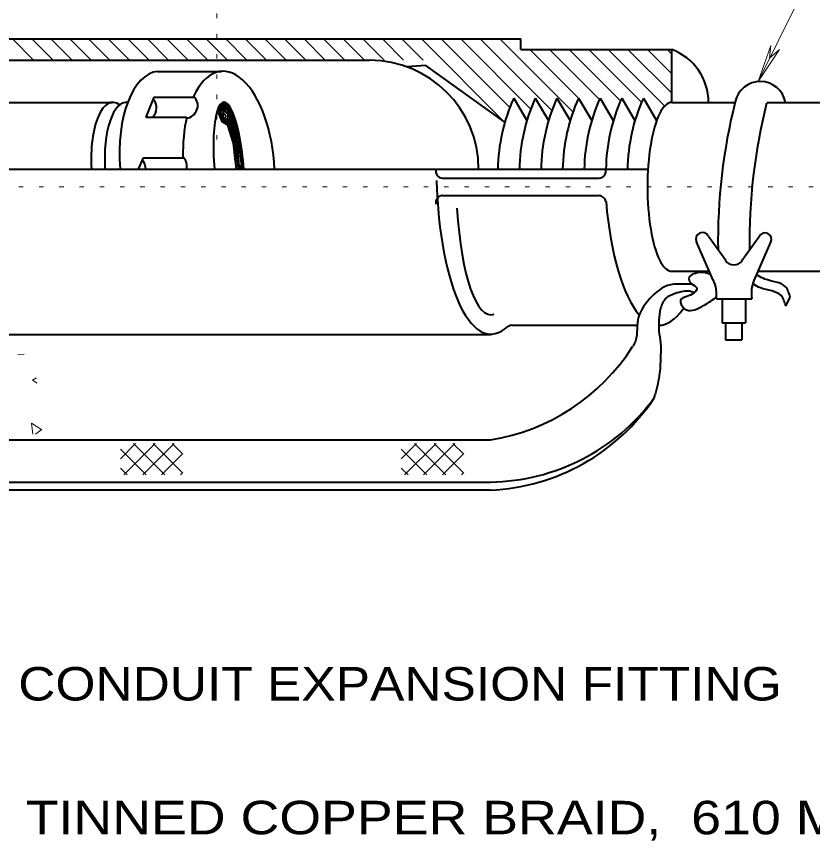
# Model space of a CAD drawing. Extents: x 312583 to 312854, y 144419 to 144597.
# Drawn here: x 312729.23 to 312747.3, y 144539.88 to 144558.59 of the extents above; entities that cross this region are included whole.
import ezdxf

# ---------------------------------------------------------------- set-up
doc = ezdxf.new("R2010")
doc.units = 0
doc.header["$LTSCALE"] = 0.3
doc.linetypes.add('DOTTED', pattern=[1.5, 0.3, -1.2])
doc.layers.add('1', color=7, linetype='Continuous', lineweight=40)
doc.layers.add('2', color=7, linetype='Continuous', lineweight=13)

msp = doc.modelspace()

# ---------------------------------------------------------------- linework, layer by layer
at = {"layer": '1'}
for p, q in [((312727.4098, 144558.076), (312740.6808, 144558.076)), ((312740.6808, 144557.8383), (312740.6808, 144558.076)), ((312740.6808, 144557.8383), (312744.1078, 144557.8383)), ((312744.1078, 144556.6347), (312744.1078, 144557.8383)), ((312724.8721, 144557.593), (312737.2461, 144557.593)), ((312732.4391, 144557.34), (312733.8804, 144557.34)), ((312715.7104, 144556.6347), (312731.4041, 144556.6347)), ((312732.3471, 144556.7573), (312732.1631, 144556.2973)), ((312732.3471, 144556.7573), (312733.2671, 144556.7573)), ((312740.5198, 144556.7343), (312740.8188, 144556.2207)), ((312741.0104, 144556.7343), (312741.3094, 144556.2207)), ((312741.5011, 144556.7343), (312741.8001, 144556.2207)), ((312741.9918, 144556.7343), (312742.2908, 144556.2207)), ((312742.4824, 144556.7343), (312742.7814, 144556.2207)), ((312742.9731, 144556.7343), (312743.2721, 144556.2207)), ((312743.4638, 144556.7343), (312743.7628, 144556.2207)), ((312744.1078, 144556.6347), (312745.5414, 144556.6347)), ((312746.2698, 144556.6347), (312753.1391, 144556.6347)), ((312732.1631, 144556.2973), (312733.0908, 144556.2973)), ((312732.1018, 144555.3773), (312731.9944, 144555.1167)), ((312732.1018, 144555.3773), (312733.0218, 144555.3773)), ((312726.1371, 144555.1167), (312743.5711, 144555.1167)), ((312738.9021, 144554.9173), (312742.4594, 144554.9173)), ((312738.9021, 144554.5187), (312742.4594, 144554.5187)), ((312745.0508, 144552.602), (312744.6674, 144553.4683)), ((312745.3344, 144553.0467), (312744.9434, 144553.591)), ((312745.7024, 144553.0467), (312746.0934, 144553.591)), ((312745.9784, 144552.5943), (312746.3618, 144553.4607)), ((312744.1078, 144552.8013), (312744.9588, 144552.8013)), ((312746.0704, 144552.8013), (312753.1391, 144552.8013)), ((312745.1274, 144552.1727), (312745.9248, 144552.1727)), ((312745.2501, 144552.165), (312745.2501, 144551.6283)), ((312745.7791, 144552.165), (312745.7791, 144551.6283)), ((312746.6991, 144552.0117), (312746.7988, 144552.211)), ((312740.4738, 144551.5747), (312743.3258, 144551.5747)), ((312745.2501, 144551.6283), (312745.7791, 144551.6283)), ((312745.3268, 144551.6283), (312745.3268, 144551.245)), ((312745.7024, 144551.6283), (312745.7024, 144551.245)), ((312726.9498, 144551.3677), (312739.9908, 144551.3677)), ((312745.3268, 144551.245), (312745.7024, 144551.245)), ((312723.0398, 144548.9757), (312739.9908, 144548.9757)), ((312723.0398, 144548.0173), (312739.9908, 144548.0173)), ((312723.0398, 144547.841), (312739.9908, 144547.841))]:
    msp.add_line(p, q, dxfattribs=at)
at = {"layer": '1', "linetype": 'DOTTED', "lineweight": 13}
msp.add_line((312711.3404, 144554.718), (312753.1391, 144554.718), dxfattribs=at)
at = {"layer": '1'}
for points in [[(312740.3204, 144556.19), (312738.5264, 144557.4703), (312738.0971, 144557.4397)], [(312734.3864, 144555.1167), (312734.2254, 144555.1167), (312734.1948, 144555.362), (312734.1564, 144555.707), (312734.0261, 144556.121), (312733.9034, 144556.19), (312733.8498, 144556.328), (312733.7884, 144556.4123), (312733.8804, 144556.5887), (312733.9571, 144556.6117), (312734.0951, 144556.466), (312734.1794, 144556.2053), (312734.2944, 144555.7683), (312734.3328, 144555.431), (312734.3634, 144555.1473), (312734.2714, 144555.1397), (312734.2024, 144555.6533), (312734.0491, 144556.121), (312733.9264, 144556.1977), (312733.8804, 144556.3587), (312733.8191, 144556.3817), (312733.9034, 144556.5503), (312733.9571, 144556.581), (312734.0721, 144556.466), (312734.2714, 144555.73), (312734.3404, 144555.1857), (312734.2868, 144555.1857), (312734.2484, 144555.6763), (312734.0874, 144556.121), (312733.9188, 144556.213), (312733.9188, 144556.3663), (312733.8574, 144556.4123), (312733.9494, 144556.5503), (312734.0184, 144556.4507), (312734.2254, 144555.776), (312734.0414, 144556.1977), (312733.9648, 144556.213), (312733.9801, 144556.3357), (312733.9188, 144556.397), (312733.9571, 144556.4507), (312734.0031, 144556.3893), (312734.0721, 144556.4353), (312734.0798, 144556.2513), (312734.0261, 144556.2207), (312734.0338, 144556.3357), (312734.0414, 144556.466), (312733.9188, 144556.489), (312733.9111, 144556.282), (312734.0031, 144556.2513), (312734.0951, 144556.1593)]]:
    msp.add_lwpolyline(points, dxfattribs=at)
for centre, radius, start, end in [((312743.6525, 144556.6292), 1.292, 0.24072, 69.36647), ((312737.2461, 144555.1167), 2.4763, 0, 90), ((312746.1187, 144556.5275), 0.5827, 10.59906, 167.86288), ((312732.1141, 144556.512), 0.2945, 313.20051, 42.47617), ((312733.0494, 144556.5657), 0.2945, 277.96991, 42.47617), ((312744.2408, 144555.055), 4.0824, 155.71072, 179.13516), ((312744.7315, 144555.055), 4.0824, 155.71072, 179.13516), ((312745.2222, 144555.055), 4.0824, 155.71072, 179.13516), ((312745.7128, 144555.055), 4.0824, 155.71072, 179.13516), ((312746.2035, 144555.055), 4.0824, 155.71072, 179.13516), ((312746.6942, 144555.055), 4.0824, 155.71072, 179.13516), ((312747.1848, 144555.055), 4.0824, 155.71072, 179.13516), ((312758.1933, 144553.4784), 13.0359, 165.91883, 180.82259), ((312758.9063, 144553.4477), 13.0359, 165.91883, 180.72864), ((312731.8687, 144555.132), 0.2945, 357.01533, 42.47617), ((312732.8041, 144555.1857), 0.2945, 346.44908, 42.47617), ((312738.9021, 144555.0707), 0.1533, 165.25644, 270), ((312742.4594, 144555.0707), 0.1533, 270, 14.74356), ((312738.9021, 144554.3653), 0.1533, 90, 194.74356), ((312742.4594, 144554.3653), 0.1533, 6.34019, 90), ((312744.8054, 144553.5297), 0.151, 27.89727, 203.96249), ((312746.2238, 144553.522), 0.151, 336.03751, 152.10273), ((312745.5184, 144553.1771), 0.23, 215.31121, 324.68879), ((312744.2841, 144552.257), 0.8438, 354.28941, 24.22774), ((312746.7604, 144552.2953), 0.8438, 159.26129, 188.35075), ((312740.4738, 144551.4213), 0.1533, 90, 126.8699), ((312739.2535, 144553.6179), 4.7005, 279.02485, 327.49763), ((312739.928, 144552.7174), 4.7005, 270.76554, 323.52738), ((312739.7975, 144552.5321), 4.7005, 272.35877, 326.33013), ((312743.2223, 144550.1142), 0.5218, 338.90205, 347.69946)]:
    msp.add_arc(centre, radius, start, end, dxfattribs=at)
for centre, major_axis, ratio, start_param, end_param in [((312732.609, 144555.1982), (-0.1699, 2.1418), 0.480227, 6.2831853, 7.8539816), ((312734.0503, 144555.1982), (-0.1699, 2.1418), 0.480227, 4.6363619, 6.991541), ((312731.4773, 144555.1827), (-0.0732, 1.452), 0.377783, 5.9815228, 7.8802166), ((312731.784, 144555.1827), (-0.0732, 1.452), 0.377783, 6.2064649, 7.8802166), ((312734.0503, 144555.1982), (-0.1145, 1.4434), 0.228731, 4.6374354, 7.8923792), ((312744.1078, 144554.718), (0, 1.9167), 0.288, 6.2831853, 9.424778), ((312734.0503, 144555.1982), (-0.1699, 2.1418), 0.480227, 0.9927836, 1.4420674), ((312740.0903, 144555.5141), (-0.0995, -4.1388), 0.320432, 4.8776978, 6.5794282), ((312743.9006, 144555.7134), (-0.0995, -4.1388), 0.320432, 5.047256, 5.9492776), ((312740.0903, 144555.5141), (-0.089, -3.7001), 0.239872, 5.0717848, 6.3660556), ((312743.9006, 144555.7134), (-0.0995, -4.1388), 0.320432, 0.0115571, 0.4347576)]:
    msp.add_ellipse(centre, major_axis=major_axis, ratio=ratio, start_param=start_param, end_param=end_param, dxfattribs=at)
for points in [[(312745.0048, 144552.7247), (312744.7211, 144552.7707), (312744.4988, 144552.6327), (312744.5601, 144552.5177), (312744.6751, 144552.4257), (312744.5754, 144552.28), (312744.3071, 144552.142), (312744.3991, 144551.9503), (312744.7824, 144551.9963), (312745.1121, 144552.2033)], [(312746.7988, 144552.211), (312746.6914, 144552.4487), (312746.2238, 144552.625), (312746.0628, 144552.7093)], [(312744.5678, 144552.51), (312744.2534, 144552.51), (312744.0771, 144552.4947), (312743.6018, 144552.1727), (312743.3411, 144551.6973), (312743.2568, 144551.153), (312743.2184, 144551.0917)], [(312746.6991, 144552.0117), (312746.5918, 144552.2493), (312746.1241, 144552.4257), (312745.9631, 144552.51)], [(312744.6061, 144552.3183), (312744.5141, 144552.349), (312744.3684, 144552.3413), (312744.1844, 144552.2953), (312743.9851, 144552.1957), (312743.8548, 144551.9657), (312743.8164, 144551.6897), (312743.8164, 144551.452), (312743.8548, 144551.1683), (312743.8548, 144550.9), (312743.8318, 144550.486), (312743.7321, 144550.003)]]:
    msp.add_spline(points, degree=3, dxfattribs=at)
at = {"layer": '2', "linetype": 'DOTTED'}
msp.add_line((312733.7808, 144555.7913), (312733.7808, 144564.9453), dxfattribs=at)
at = {"layer": '2'}
for p, q in [((312748.2938, 144561.5873), (312746.0704, 144557.11)), ((312729.6178, 144557.593), (312729.1348, 144558.076)), ((312730.0624, 144557.593), (312729.5794, 144558.076)), ((312730.4918, 144557.593), (312730.0088, 144558.076)), ((312730.9211, 144557.593), (312730.4381, 144558.076)), ((312731.3504, 144557.593), (312730.8674, 144558.076)), ((312731.7951, 144557.593), (312731.3121, 144558.076)), ((312732.2398, 144557.593), (312731.7568, 144558.076)), ((312732.6844, 144557.593), (312732.2014, 144558.076)), ((312733.1291, 144557.593), (312732.6461, 144558.076)), ((312733.5738, 144557.593), (312733.0908, 144558.076)), ((312734.0184, 144557.593), (312733.5354, 144558.076)), ((312734.4631, 144557.593), (312733.9801, 144558.076)), ((312734.9078, 144557.593), (312734.4248, 144558.076)), ((312735.3524, 144557.593), (312734.8694, 144558.076)), ((312735.7971, 144557.593), (312735.3141, 144558.076)), ((312736.2418, 144557.593), (312735.7588, 144558.076)), ((312736.6864, 144557.593), (312736.2034, 144558.076)), ((312737.1311, 144557.593), (312736.6481, 144558.076)), ((312737.5758, 144557.593), (312737.0928, 144558.076)), ((312738.0204, 144557.593), (312737.5374, 144558.076)), ((312738.4651, 144557.593), (312737.9821, 144558.076)), ((312740.2974, 144556.2053), (312738.4268, 144558.076)), ((312740.4278, 144556.5197), (312738.8714, 144558.076)), ((312740.9108, 144556.4813), (312739.3161, 144558.076)), ((312741.3861, 144556.4507), (312739.7608, 144558.076)), ((312741.8614, 144556.42), (312740.2054, 144558.076)), ((312746.0704, 144557.11), (312746.3618, 144557.9303)), ((312746.3618, 144557.9303), (312746.3311, 144557.639)), ((312741.9918, 144556.7343), (312740.8878, 144557.8383)), ((312742.4671, 144556.7037), (312741.3324, 144557.8383)), ((312742.9424, 144556.673), (312741.7771, 144557.8383)), ((312743.4254, 144556.6347), (312742.2218, 144557.8383)), ((312743.9468, 144556.558), (312742.6664, 144557.8383)), ((312744.1078, 144556.8417), (312743.1111, 144557.8383)), ((312744.1078, 144557.2863), (312743.5558, 144557.8383)), ((312744.1078, 144557.731), (312744.0004, 144557.8383)), ((312746.0704, 144557.11), (312746.5534, 144557.8383)), ((312746.5534, 144557.8383), (312746.3311, 144557.639)), ((312729.2574, 144550.9153), (312729.4031, 144550.923)), ((312731.5881, 144548.5463), (312731.9331, 144548.8913)), ((312732.1708, 144548.1783), (312731.5881, 144548.761)), ((312731.6648, 144548.1783), (312732.3778, 144548.8913)), ((312732.6001, 144548.1783), (312731.8871, 144548.8913)), ((312732.0941, 144548.1783), (312732.8071, 144548.8913)), ((312733.0064, 144548.2167), (312732.3318, 144548.8913)), ((312733.0064, 144548.646), (312732.7611, 144548.8913)), ((312737.9668, 144548.5463), (312738.3118, 144548.8913)), ((312738.5494, 144548.1783), (312737.9668, 144548.761)), ((312738.0434, 144548.1783), (312738.7564, 144548.8913)), ((312738.9788, 144548.1783), (312738.2658, 144548.8913)), ((312738.4728, 144548.1783), (312739.1858, 144548.8913)), ((312739.3851, 144548.2167), (312738.7104, 144548.8913)), ((312739.3851, 144548.646), (312739.1398, 144548.8913)), ((312732.5234, 144548.1783), (312733.0064, 144548.6613)), ((312738.9021, 144548.1783), (312739.3851, 144548.6613)), ((312731.7414, 144548.1783), (312731.5881, 144548.3317)), ((312732.9528, 144548.1783), (312733.0064, 144548.232)), ((312738.1201, 144548.1783), (312737.9668, 144548.3317)), ((312739.3314, 144548.1783), (312739.3851, 144548.232))]:
    msp.add_line(p, q, dxfattribs=at)
for points in [[(312729.6868, 144550.3863), (312729.5948, 144550.3327), (312729.7021, 144550.2637)], [(312729.8018, 144549.2057), (312729.7788, 144549.221), (312729.5718, 144549.3513), (312729.6024, 144549.106)], [(312729.6638, 144549.106), (312729.7788, 144549.198), (312729.8018, 144549.2057)]]:
    msp.add_lwpolyline(points, dxfattribs=at)

# ---------------------------------------------------------------- texts
for s, width, p in [('CONDUIT EXPANSION FITTING', 1.15, (312729.2693, 144543.0576)), ('TINNED COPPER BRAID,  610 MM LG.', 1.2, (312729.438, 144540.0203))]:
    msp.add_text(s, height=0.76, dxfattribs=dict(at, width=width)).set_placement(p)

doc.saveas('drawing.dxf')
